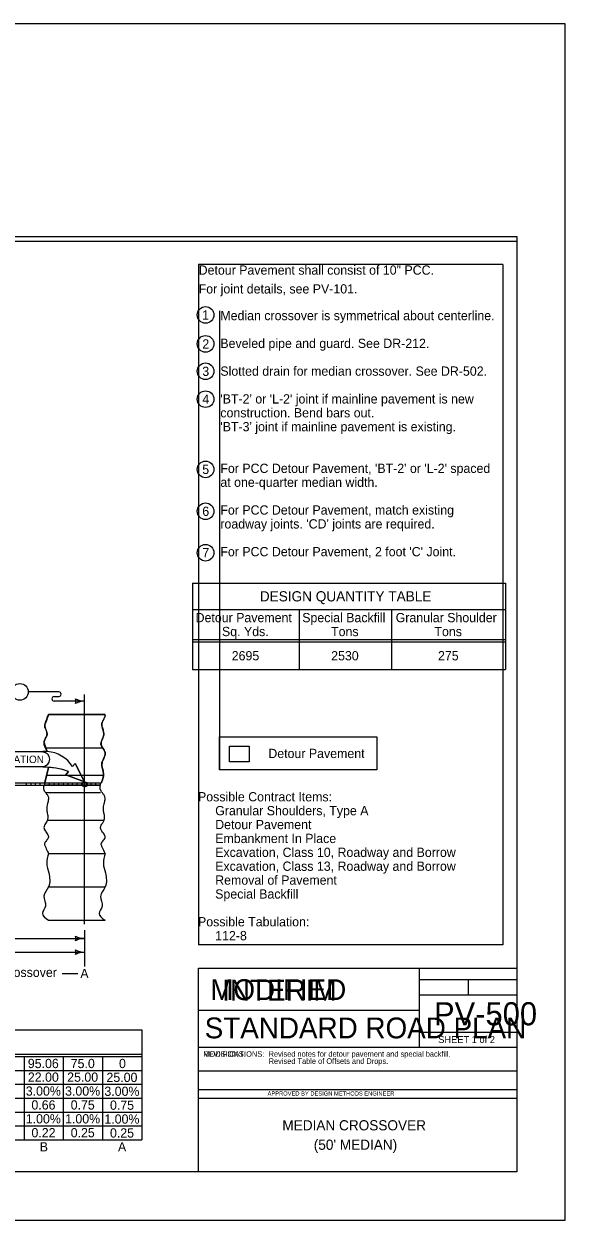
# Model space of a CAD drawing. Extents: x 10028 to 81668, y 3581 to 11018.
# Drawn here: x 12202 to 13372, y 7820 to 10404 of the extents above; entities that cross this region are included whole.
import ezdxf

# ---------------------------------------------------------------- set-up
doc = ezdxf.new("R2010")
doc.units = 0
for name, color, linetype in [('dsnCellElements', 7, 'Continuous'), ('dsnCellsNorthArrow', 7, 'Continuous'), ('DsnShtRevisedText', 7, 'Continuous'), ('dsnstdblockInterim', 7, 'Continuous'), ('dsnStdBlockModified', 7, 'Continuous'), ('dsnStdLabel', 7, 'Continuous'), ('dsnStdNameDate', 7, 'Continuous'), ('dsnStdShading', 7, 'Continuous'), ('dsnTextFinalPlan', 7, 'Continuous'), ('dsnTextTabulation', 7, 'Continuous'), ('Level 10', 7, 'Continuous'), ('Level 11', 7, 'Continuous'), ('Level 12', 7, 'Continuous'), ('Level 6', 7, 'Continuous'), ('Level 7', 7, 'Continuous'), ('Level 8', 7, 'Continuous'), ('Level 9', 7, 'Continuous'), ('SheetAddendum', 7, 'Continuous'), ('SheetBorder', 7, 'Continuous'), ('ShtPlotIdentification', 7, 'Continuous'), ('Text', 7, 'Continuous')]:
    doc.layers.add(name, color=color, linetype=linetype)

msp = doc.modelspace()

# ---------------------------------------------------------------- linework, layer by layer
at = {"layer": 'dsnCellElements'}
msp.add_line((12566.5, 9138.3), (13243.3, 9138.3), dxfattribs=at)
at = {"layer": 'dsnCellsNorthArrow'}
for p, q in [((12332.9, 8458.6), (12332.9, 8955)), ((12254.6, 8539.5), (12377.4, 8539.5))]:
    msp.add_line(p, q, dxfattribs=at)
at = {"layer": 'DsnShtRevisedText'}
msp.add_lwpolyline([(10132.5, 9934), (13267.5, 9934), (13267.5, 7924), (10132.5, 7924)], close=True, dxfattribs=at)
at = {"layer": 'dsnStdLabel'}
for p, q in [((12249.9, 8831.2), (12042.4, 8831.2)), ((12251.9, 8831.7), (12242.4, 8832.1)), ((12242.4, 8832.1), (12242.4, 8830.3)), ((12249.9, 8798.7), (12042.3, 8798.7)), ((12242.4, 8799.6), (12242.4, 8797.8)), ((12298.3, 8788.5), (12292.4, 8781.2)), ((12312.4, 8806.2), (12306.8, 8799.1)), ((12332.4, 8766.2), (12312.4, 8806.2)), ((12292.4, 8781.2), (12332.4, 8766.2))]:
    msp.add_line(p, q, dxfattribs=at)
for centre, radius, start, end in [((12242.4, 8814.9), 15.3, 270, 90), ((12247.3, 8761.4), 70.4, 32.3953, 86.3054), ((12245.2, 8641.7), 156.1, 70.133, 91.0368)]:
    msp.add_arc(centre, radius, start, end, dxfattribs=at)
at = {"layer": 'dsnStdShading'}
for p, q in [((12377.1, 8911.5), (12254.6, 8911.5)), ((12646.2, 8843.1), (12688.9, 8843.1)), ((12646.2, 8809.4), (12646.2, 8843.1)), ((12688.9, 8843.1), (12688.9, 8809.4)), ((12254.6, 8797.5), (12246.7, 8763.9)), ((12292.4, 8781.2), (12298.3, 8788.5)), ((12306.8, 8799.1), (12312.4, 8806.2)), ((12312.4, 8806.2), (12332.4, 8766.2)), ((12688.9, 8809.4), (12646.2, 8809.4)), ((12332.4, 8766.2), (12292.4, 8781.2)), ((12254.6, 8611.5), (12377.1, 8611.5))]:
    msp.add_line(p, q, dxfattribs=at)
for points in [[(12246.7, 8763.9), (12246.9, 8763.9), (12256.9, 8763.9), (12266.9, 8763.9), (12276.9, 8763.9), (12286.9, 8763.9), (12296.9, 8763.9), (12306.9, 8763.9), (12316.9, 8763.9), (12326.9, 8763.9), (12336.9, 8763.9), (12346.9, 8763.9), (12356.9, 8763.9), (12366.9, 8763.9), (12369.2, 8763.9)], [(12367.5, 8759.1), (12366.9, 8759.1), (12356.9, 8759.1), (12346.9, 8759.1), (12336.9, 8759.1), (12326.9, 8759.1), (12316.9, 8759.1), (12306.9, 8759.1), (12296.9, 8759.1), (12286.9, 8759.1), (12276.9, 8759.1), (12266.9, 8759.1), (12256.9, 8759.1), (12246.9, 8759.1), (12245.2, 8759.1)]]:
    msp.add_lwpolyline(points, dxfattribs=at)
for centre, radius, start, end in [((12247.3, 8761.4), 70.4, 32.3953, 86.258), ((12245.2, 8641.7), 156.1, 70.133, 86.5437)]:
    msp.add_arc(centre, radius, start, end, dxfattribs=at)
for points in [[(12254.6, 8911.5), (12252.2, 8904.7), (12249.9, 8898), (12247.5, 8891.2), (12247.1, 8890), (12246.8, 8888.6), (12246.8, 8887.3), (12246.9, 8885.5), (12247.4, 8883.7), (12248, 8881.9), (12248.8, 8879.3), (12250, 8877), (12250.8, 8874.4), (12251.2, 8873), (12251.5, 8871.6), (12251.6, 8870.2), (12251.7, 8868.6), (12251.5, 8866.9), (12250.8, 8865.3), (12250, 8863.5), (12249.1, 8862), (12248.3, 8860.3), (12247.4, 8858.3), (12246.5, 8856.3), (12245.6, 8854.3), (12245.2, 8853.3), (12244.8, 8852.1), (12245.2, 8851), (12247.4, 8844.6), (12249.7, 8838.1), (12251.9, 8831.7)], [(12370.4, 8767.2), (12371, 8769.1), (12371.6, 8771), (12372.1, 8772.9), (12372.7, 8774.7), (12373.1, 8776.5), (12373.5, 8778.4), (12374, 8781), (12373.8, 8783.8), (12373.3, 8786.5), (12372.8, 8788.5), (12372.4, 8790.6), (12371.9, 8792.7), (12371.5, 8794.5), (12371, 8796.3), (12370.6, 8798.1), (12369.8, 8801.7), (12369.7, 8805.8), (12371.1, 8809.3), (12372.1, 8812), (12373.2, 8814.6), (12374.4, 8817.3), (12374.6, 8817.9), (12374.9, 8818.6), (12375.2, 8819.2), (12376, 8821.1), (12376.6, 8823.2), (12377.1, 8825.2), (12377.4, 8826.5), (12377.4, 8828), (12377, 8829.3), (12376.6, 8831.1), (12375.9, 8832.8), (12374.9, 8834.4), (12374, 8836), (12373, 8837.5), (12372, 8839), (12371.2, 8840.5), (12370.4, 8841.9), (12369.6, 8843.4), (12368.5, 8845.5), (12367.9, 8847.9), (12368.4, 8850.1), (12369.2, 8853.1), (12370.3, 8856), (12371.4, 8859), (12372, 8860.5), (12372.7, 8861.9), (12373.2, 8863.4), (12374.1, 8866), (12374.6, 8868.7), (12374.2, 8871.3), (12373.8, 8873.7), (12373.2, 8876.1), (12372.6, 8878.5), (12372.1, 8880), (12371.6, 8881.4), (12371.2, 8883), (12370.6, 8885.1), (12370.3, 8887.3), (12370, 8889.5), (12369.9, 8891.1), (12370.1, 8892.8), (12370.7, 8894.3), (12371.9, 8897.2), (12373.5, 8899.6), (12374.7, 8902.4), (12375.5, 8904.2), (12376.7, 8905.9), (12377, 8907.8), (12377.1, 8908.4), (12377.2, 8909.1), (12377.3, 8909.7)], [(12369.2, 8763.9), (12369.4, 8764.4), (12369.6, 8764.9), (12369.7, 8765.4), (12370, 8766), (12370.2, 8766.6), (12370.4, 8767.2)]]:
    msp.add_open_spline(points, degree=3, dxfattribs=at)
for points in [[(12377.3, 8909.7), (12377.3, 8910.7), (12377.2, 8911.3), (12377.1, 8911.5)], [(12245.2, 8759.1), (12243.7, 8752.4), (12244.3, 8749), (12246.7, 8745), (12250.7, 8739.8), (12253.9, 8734.6), (12254.5, 8728.9), (12252.4, 8719.2), (12251.1, 8713.1), (12250.8, 8708.2), (12251.7, 8700.7), (12253.3, 8690.8), (12253.2, 8686.9), (12250.8, 8680.9), (12248, 8676.2), (12246, 8672.4), (12244.8, 8667.4), (12245.7, 8663.7), (12250.6, 8656.2), (12253.3, 8651.9), (12254.5, 8648.3), (12254.1, 8645.1), (12251.4, 8640.9), (12248.7, 8637.4), (12247, 8634.9), (12246.2, 8632.6), (12246.2, 8630.4), (12247.6, 8627.1), (12250, 8621.7), (12252.8, 8615.6), (12254.6, 8611.5)], [(12377.1, 8611.5), (12371.7, 8623.5), (12369.2, 8629.2), (12368.8, 8631.4), (12370.6, 8636), (12372.3, 8638.4), (12375, 8641.7), (12377.1, 8645.9), (12376.7, 8649.9), (12375, 8653.3), (12371.8, 8657.8), (12368.9, 8662.3), (12367.5, 8666.4), (12367.8, 8669.9), (12370.1, 8674.9), (12373.6, 8680.7), (12375.1, 8684), (12376, 8688.1), (12375.5, 8694.6), (12374, 8702.6), (12373.5, 8707.3), (12375.2, 8718.9), (12376.8, 8725.8), (12377.2, 8731), (12375.7, 8736.1), (12372.3, 8741.1), (12368.7, 8746), (12366.8, 8750), (12366.5, 8752.7), (12367.5, 8759.1)]]:
    msp.add_spline(points, degree=3, dxfattribs=at)
at = {"layer": 'dsnTextFinalPlan'}
for p, q in [((12277, 8960.6), (12210.8, 8960.6)), ((12267, 8950.6), (12277, 8950.6)), ((12333.1, 8940.6), (12267, 8940.6)), ((12111.8, 8428.1), (12332.9, 8428.1)), ((12332.9, 8446.1), (12332.9, 8367.2)), ((11380, 8398.1), (12332.9, 8398.1)), ((12284.2, 8352.2), (12317.9, 8352.2))]:
    msp.add_line(p, q, dxfattribs=at)
msp.add_circle((12333.1, 8760.8), 5.33, dxfattribs=at)
for centre, radius, start, end in [((12267, 8945.6), 5, 90, 270), ((12277, 8955.6), 5, 270, 90), ((12297.4, 8940.6), 16.4, 342.2666, 17.7333), ((12333.1, 8983.1), 42.5, 241.9275, 270), ((12333.1, 8898.1), 42.5, 90, 118.0725), ((12297.3, 8428.1), 16.4, 342.2666, 17.7333), ((12332.9, 8470.6), 42.5, 241.9275, 270), ((12332.9, 8385.6), 42.5, 90, 118.0725), ((12297.3, 8398.1), 16.4, 342.2666, 17.7333), ((12332.9, 8440.6), 42.5, 241.9275, 270), ((12332.9, 8355.6), 42.5, 90, 118.0725)]:
    msp.add_arc(centre, radius, start, end, dxfattribs=at)
at = {"layer": 'dsnTextTabulation'}
for p, q in [((12796.5, 9138.3), (12796.5, 9008.6)), ((12996.5, 9138.3), (12996.5, 9008.6)), ((12566.5, 9073.6), (13243.3, 9073.6)), ((12566.5, 9068.6), (13243.3, 9068.6)), ((12646.2, 8843.1), (12688.9, 8843.1)), ((12646.2, 8809.4), (12646.2, 8843.1)), ((12688.9, 8843.1), (12688.9, 8809.4)), ((12688.9, 8809.4), (12646.2, 8809.4)), ((10212.7, 8177.8), (12456.8, 8177.8)), ((10212.7, 8172.8), (12456.8, 8172.8)), ((12201.8, 8172.8), (12201.8, 7992.8)), ((12286.8, 8172.8), (12286.8, 7992.8)), ((12371.8, 8172.8), (12371.8, 7992.8))]:
    msp.add_line(p, q, dxfattribs=at)
for centre in [(12594.5, 9774.8), (12594.5, 9712.3), (12594.5, 9653.1), (12594.5, 9592.9), (12594.5, 9441.2), (12594.5, 9350.7), (12594.5, 9261.1)]:
    msp.add_circle(centre, 18, dxfattribs=at)
at = {"layer": 'Level 10'}
msp.add_circle((12192.8, 8960.6), 18, dxfattribs=at)
at = {"layer": 'Level 11'}
for p, q in [((10212.7, 8230.8), (12456.8, 8230.8)), ((12456.8, 8230.8), (12456.8, 7992.8)), ((10212.7, 7992.8), (12456.8, 7992.8))]:
    msp.add_line(p, q, dxfattribs=at)
at = {"layer": 'Level 12'}
for p, q in [((12566.5, 9195.6), (12566.5, 9008.6)), ((12566.5, 9195.6), (13243.3, 9195.6)), ((13243.3, 9195.6), (13243.3, 9008.6)), ((12566.5, 9008.6), (13243.3, 9008.6))]:
    msp.add_line(p, q, dxfattribs=at)
msp.add_lwpolyline([(12624.5, 8863.3), (12965.1, 8863.3), (12965.1, 8792.5), (12624.5, 8792.5)], close=True, dxfattribs=at)
at = {"layer": 'Level 8'}
for p, q in [((12579.5, 9884), (12579.5, 8414)), ((13237.5, 9884), (12579.5, 9884)), ((13237.5, 9884), (13237.5, 8414)), ((12624.5, 9784), (12624.5, 8792.5)), ((13237.5, 8414), (12579.5, 8414))]:
    msp.add_line(p, q, dxfattribs=at)
at = {"layer": 'Level 9'}
for p, q in [((10212.7, 8142.8), (12456.8, 8142.8)), ((10212.7, 8112.8), (12456.8, 8112.8)), ((10212.7, 8082.8), (12456.8, 8082.8)), ((10212.7, 8052.8), (12456.8, 8052.8)), ((10212.7, 8022.8), (12456.8, 8022.8))]:
    msp.add_line(p, q, dxfattribs=at)
at = {"layer": 'SheetAddendum'}
for p, q in [((12254.6, 8911.5), (12377.1, 8911.5)), ((12249.2, 8839.5), (12371.8, 8839.5)), ((12246.9, 8764.5), (12254.6, 8797.5)), ((12041.2, 8763.9), (12369.2, 8763.9)), ((12206.9, 8759.1), (12206.9, 8763.9)), ((12216.9, 8759.1), (12216.9, 8763.9)), ((12226.9, 8759.1), (12226.9, 8763.9)), ((12236.9, 8759.1), (12236.9, 8763.9)), ((12246.9, 8759.1), (12246.9, 8763.9)), ((12250.2, 8780.3), (12372.9, 8780.3)), ((12256.9, 8759.1), (12256.9, 8763.9)), ((12266.9, 8759.1), (12266.9, 8763.9)), ((12276.9, 8759.1), (12276.9, 8763.9)), ((12286.9, 8759.1), (12286.9, 8763.9)), ((12296.9, 8759.1), (12296.9, 8763.9)), ((12306.9, 8759.1), (12306.9, 8763.9)), ((12316.9, 8759.1), (12316.9, 8763.9)), ((12326.9, 8759.1), (12326.9, 8763.9)), ((12336.9, 8759.1), (12336.9, 8763.9)), ((12346.9, 8759.1), (12346.9, 8763.9)), ((12356.9, 8759.1), (12356.9, 8763.9)), ((12366.9, 8759.1), (12366.9, 8763.9)), ((12041.2, 8759.1), (12367.4, 8759.1)), ((12248.7, 8743.5), (12367.5, 8743.5)), ((12252.1, 8683.5), (12374, 8683.5)), ((12254.6, 8611.5), (12377.1, 8611.5)), ((12254.6, 8467.5), (12376.9, 8467.5))]:
    msp.add_line(p, q, dxfattribs=at)
for points in [[(12251.9, 8831.6), (12245.2, 8851), (12245.6, 8854.3), (12248.3, 8860.3), (12250.8, 8865.3), (12251.6, 8870.2), (12250.8, 8874.4), (12248, 8881.9), (12246.8, 8887.3), (12247.5, 8891.2), (12254.6, 8911.5)], [(12377.3, 8909.7), (12377, 8907.8), (12374.7, 8902.4), (12370.7, 8894.3), (12370, 8889.5), (12371.2, 8883), (12372.6, 8878.5), (12374.2, 8871.3), (12373.2, 8863.4), (12371.4, 8859), (12368.4, 8850.1), (12369.6, 8843.4), (12372, 8839), (12374.9, 8834.4), (12377, 8829.3), (12377.1, 8825.2), (12375.2, 8819.2), (12374.4, 8817.3), (12371.1, 8809.3), (12370.6, 8798.1), (12371.9, 8792.7), (12373.3, 8786.5), (12373.5, 8778.4), (12372.1, 8772.9), (12370.4, 8767.1)], [(12377.3, 8909.6), (12377.3, 8910.7), (12377.2, 8911.3), (12377.1, 8911.5)], [(12370.4, 8767.2), (12369.7, 8765.4), (12369.2, 8763.9)], [(12245.2, 8759.1), (12243.7, 8752.4), (12244.3, 8749), (12246.7, 8745), (12250.7, 8739.8), (12253.9, 8734.6), (12254.5, 8728.9), (12252.4, 8719.2), (12251.1, 8713.1), (12250.8, 8708.2), (12251.7, 8700.7), (12253.3, 8690.8), (12253.2, 8686.9), (12250.8, 8680.9), (12248, 8676.2), (12246, 8672.4), (12244.8, 8667.4), (12245.7, 8663.7), (12250.6, 8656.2), (12253.3, 8651.9), (12254.5, 8648.3), (12254.1, 8645.1), (12251.4, 8640.9), (12248.7, 8637.4), (12247, 8634.9), (12246.2, 8632.6), (12246.2, 8630.4), (12247.6, 8627.1), (12250, 8621.7), (12252.8, 8615.6), (12254.6, 8611.5)], [(12377.1, 8611.5), (12371.7, 8623.5), (12369.2, 8629.2), (12368.8, 8631.4), (12370.6, 8636), (12372.3, 8638.4), (12375, 8641.7), (12377.1, 8645.9), (12376.7, 8649.9), (12375, 8653.3), (12371.8, 8657.8), (12368.9, 8662.3), (12367.5, 8666.4), (12367.8, 8669.9), (12370.1, 8674.9), (12373.6, 8680.7), (12375.1, 8684), (12376, 8688.1), (12375.5, 8694.6), (12374, 8702.6), (12373.5, 8707.3), (12375.2, 8718.9), (12376.8, 8725.8), (12377.2, 8731), (12375.7, 8736.1), (12372.3, 8741.1), (12368.7, 8746), (12366.8, 8750), (12366.5, 8752.7), (12367.5, 8759.1)], [(12254.6, 8611.5), (12250.8, 8590.3), (12255.1, 8569.7), (12254.6, 8539.5), (12244.8, 8519.2), (12248.2, 8497.8), (12241.4, 8482.4), (12254.6, 8467.5)], [(12377.1, 8611.5), (12373.4, 8589.9), (12377.7, 8569.4), (12377.2, 8539.1), (12367.5, 8518.8), (12370.9, 8497.4), (12364, 8482), (12377.2, 8467.1)]]:
    msp.add_spline(points, degree=3, dxfattribs=at)
at = {"layer": 'SheetBorder'}
msp.add_lwpolyline([(10132.5, 9944), (13267.5, 9944), (13267.5, 7924), (10132.5, 7924)], close=True, dxfattribs=at)
at = {"layer": 'ShtPlotIdentification'}
msp.add_lwpolyline([(10028, 7819.5), (13372, 7819.5), (13372, 10403.5), (10028, 10403.5)], close=True, dxfattribs=at)
at = {"layer": 'Text'}
for p, q in [((13056.6, 8364), (13056.6, 8272.7)), ((13056.6, 8339.1), (13267.5, 8339.1)), ((13162.1, 8339.1), (13162.1, 8305.9)), ((13056.6, 8305.9), (13267.5, 8305.9)), ((12579.5, 8272.7), (13056.6, 8272.7)), ((13056.6, 8272.7), (13056.6, 8192.7)), ((13267.5, 8224.9), (13056.6, 8224.9)), ((12579.5, 8192.7), (13267.5, 8192.7)), ((12579.5, 8141.7), (13267.5, 8141.7)), ((12579.5, 8101.7), (13267.5, 8101.7)), ((12579.5, 8082.7), (13267.5, 8082.7))]:
    msp.add_line(p, q, dxfattribs=at)
msp.add_lwpolyline([(12579.5, 8364), (13267.5, 8364), (13267.5, 7924), (12579.5, 7924)], close=True, dxfattribs=at)

# ---------------------------------------------------------------- texts
at = {"layer": 'dsnCellElements'}
for s, height, p in [('Detour Pavement shall consist of 10" PCC.', 20, (12579.5, 9861.8)), ('For joint details, see PV-101.', 20, (12579.5, 9821.2)), ('1', 20, (12587, 9764.8)), ('Median crossover is symmetrical about centerline.', 20, (12626.4, 9763.5)), ('2', 20, (12587.5, 9702.3)), ('Beveled pipe and guard. See DR-212.', 20, (12626.4, 9703.5)), ('Slotted drain for median crossover. See DR-502.', 20, (12626.4, 9643.5)), ('3', 20, (12587.4, 9643.1)), ('4', 20, (12587.4, 9582.9)), ("'BT-2' or 'L-2' joint if mainline pavement is new  ", 20, (12626.4, 9583.5)), ('construction. Bend bars out.', 20, (12626.4, 9553.5)), ("'BT-3' joint if mainline pavement is existing. ", 20, (12626.4, 9523.5)), ('5', 20, (12587.3, 9431.2)), ("For PCC Detour Pavement, 'BT-2' or 'L-2' spaced ", 20, (12626.4, 9433.5)), ('at one-quarter median width.', 20, (12626.4, 9403.5)), ('6', 20, (12587.4, 9340.7)), ('For PCC Detour Pavement, match existing ', 20, (12626.4, 9343.5)), ("roadway joints. 'CD' joints are required. ", 20, (12626.4, 9313.5)), ('7', 20, (12587.4, 9251.1)), ("For PCC Detour Pavement, 2 foot 'C' Joint.", 20, (12626.4, 9253.5)), ('2530', 20, (12866.1, 9028.6)), ('Possible Contract Items:', 20, (12578.1, 8724)), ('     Granular Shoulders, Type A', 20, (12578.1, 8694)), ('     Detour Pavement', 20, (12578.1, 8664)), ('     Embankment In Place', 20, (12578.1, 8634)), ('     Excavation, Class 10, Roadway and Borrow', 20, (12578.1, 8604)), ('     Excavation, Class 13, Roadway and Borrow', 20, (12578.1, 8574)), ('     Removal of Pavement', 20, (12578.1, 8544)), ('     Special Backfill', 20, (12578.1, 8514)), ('Possible Tabulation:', 20, (12578.1, 8454)), ('     112-8', 20, (12578.1, 8424)), ('MODIFICATIONS:', 12, (12589.5, 8172.3)), ('Revised notes for detour pavement and special backfill.', 12, (12730.8, 8172.4)), ('Revised Table of Offsets and Drops.', 12, (12730.8, 8156.9)), ('3.00%', 20, (12205.6, 8088.3)), ('3.00%', 20, (12290.6, 8088.3)), ('3.00%', 20, (12375.6, 8087.8)), ('0.66', 20, (12217.8, 8058.3)), ('0.75', 20, (12302.7, 8058.3)), ('0.75', 20, (12387.7, 8057.8)), ('1.00%', 20, (12205.6, 8028.3)), ('1.00%', 20, (12290.6, 8028.3)), ('1.00%', 20, (12375.6, 8027.8)), ('0.22', 20, (12217.9, 7998.3)), ('0.25', 20, (12302.7, 7998.3)), ('0.25', 20, (12387.7, 7997.8))]:
    msp.add_text(s, height=height, dxfattribs=at).set_placement(p)
at = {"layer": 'dsnstdblockInterim'}
msp.add_text('INTERIM', height=45, dxfattribs=at).set_placement((12630.5, 8293.7))
at = {"layer": 'dsnStdBlockModified'}
msp.add_text('MODIFIED', height=45, dxfattribs=at).set_placement((12604.6, 8294.8))
at = {"layer": 'dsnStdLabel'}
msp.add_text('LOCATION STATION', height=16, dxfattribs=at).set_placement((12036.6, 8806.8))
at = {"layer": 'dsnStdNameDate'}
msp.add_text('REVISIONS:', height=12, dxfattribs=at).set_placement((12589.5, 8172.3))
at = {"layer": 'Level 6'}
for s, p in [('Detour Pavement', (12572.9, 9111)), ('Special Backfill', (12803.5, 9111)), ('Granular Shoulder', (13005.6, 9111)), ('Sq. Yds.', (12629.9, 9081)), ('Tons', (12865.9, 9081)), ('Tons', (13089.4, 9081)), ('2695', (12651, 9028.6)), ('275', (13097.1, 9028.6)), ('Detour Pavement', (12730.2, 8817.6)), (' of Crossover', (12113.8, 8344.7)), ('A', (12323.6, 8342.2)), ('95.06', (12210, 8147.8)), ('75.0', (12302.8, 8147.8)), ('0', (12407.2, 8147.8)), ('22.00', (12210.1, 8118.3)), ('25.00', (12295.1, 8118.3)), ('25.00', (12380.1, 8117.8)), ('B', (12235.8, 7967.8)), ('A', (12405, 7967.8))]:
    msp.add_text(s, height=20, dxfattribs=at).set_placement(p)
at = {"layer": 'Level 7'}
msp.add_text('DESIGN QUANTITY TABLE', height=22, dxfattribs=at).set_placement((12711.8, 9156))
at = {"layer": 'Text'}
for s, height, p in [('PV-500', 50, (13088.4, 8240.2)), ('STANDARD ROAD PLAN', 45.001, (12592.5, 8212.1)), ('SHEET 1 of 2', 15, (13097.6, 8202)), ('APPROVED BY DESIGN METHODS ENGINEER', 9.003, (12728.5, 8088.5)), ('MEDIAN CROSSOVER', 22, (12760.5, 8013.3)), ("(50' MEDIAN)", 22, (12828.4, 7971.3))]:
    msp.add_text(s, height=height, dxfattribs=at).set_placement(p)

doc.saveas('drawing.dxf')
